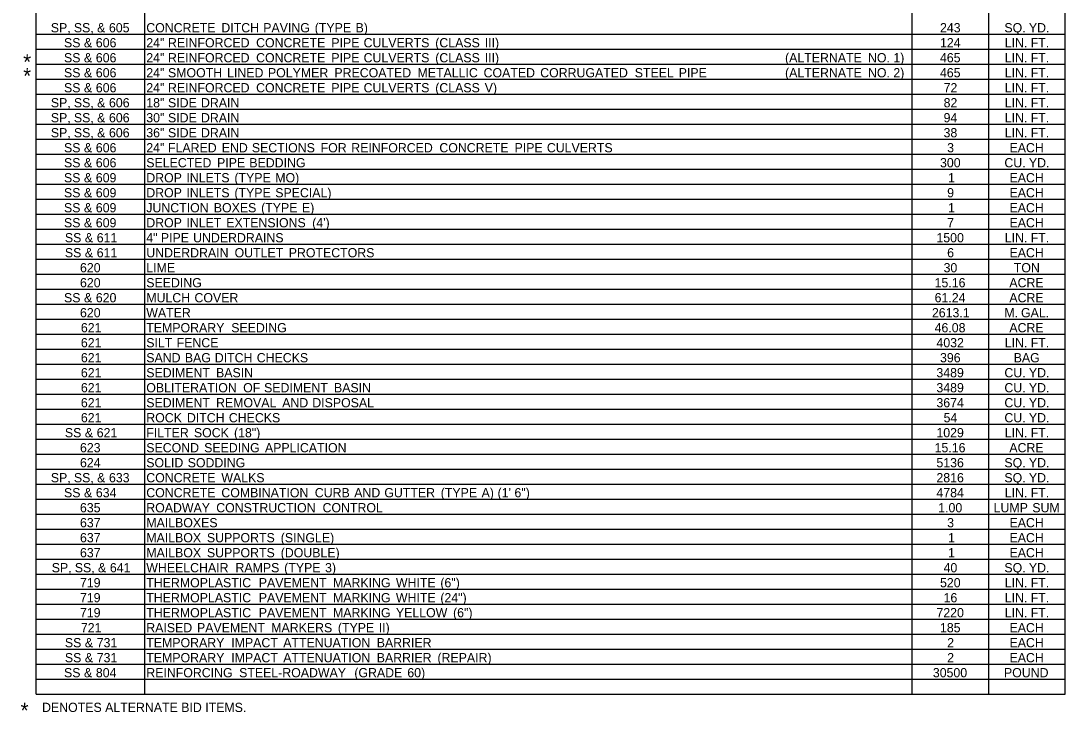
# Model space of a CAD drawing. Extents: x 1197542 to 1207068, y 230488 to 237324.
# Drawn here: x 1205572 to 1206251, y 231811 to 232261 of the extents above; entities that cross this region are included whole.
import ezdxf

# ---------------------------------------------------------------- set-up
doc = ezdxf.new("R2010")
doc.units = 0
doc.layers.add('Default', color=7, linetype='Continuous')

msp = doc.modelspace()

# ---------------------------------------------------------------- linework, layer by layer
at = {"layer": 'Default'}
for p, q in [((1205581.41, 231823.15), (1205581.41, 232690.9)), ((1205652.09, 231823.15), (1205652.09, 232690.9)), ((1206151.29, 231823.15), (1206151.29, 232690.9)), ((1206201.02, 231823.15), (1206201.02, 232690.9)), ((1206201.02, 231823.15), (1206201.02, 232690.9)), ((1206250.74, 231823.15), (1206250.74, 232690.9)), ((1205652.09, 231823.15), (1205652.09, 232661.65)), ((1206151.29, 231823.15), (1206151.29, 232661.65)), ((1205581.41, 232252.15), (1206250.74, 232252.15)), ((1205581.41, 232242.4), (1206250.74, 232242.4)), ((1205581.41, 232232.65), (1206250.74, 232232.65)), ((1205581.41, 232222.9), (1206250.74, 232222.9)), ((1205581.41, 232213.15), (1206250.74, 232213.15)), ((1205581.41, 232203.4), (1206250.74, 232203.4)), ((1205581.41, 232193.65), (1206250.74, 232193.65)), ((1205581.41, 232183.9), (1206250.74, 232183.9)), ((1205581.41, 232174.15), (1206250.74, 232174.15)), ((1205581.41, 232164.4), (1206250.74, 232164.4)), ((1205581.41, 232154.65), (1206250.74, 232154.65)), ((1205581.41, 232144.9), (1206250.74, 232144.9)), ((1205581.41, 232135.15), (1206250.74, 232135.15)), ((1205581.41, 232125.4), (1206250.74, 232125.4)), ((1205581.41, 232115.65), (1206250.74, 232115.65)), ((1205581.41, 232105.9), (1206250.74, 232105.9)), ((1205581.41, 232096.15), (1206250.74, 232096.15)), ((1205581.41, 232086.4), (1206250.74, 232086.4)), ((1205581.41, 232076.65), (1206250.74, 232076.65)), ((1205581.41, 232066.9), (1206250.74, 232066.9)), ((1205581.41, 232057.15), (1206250.74, 232057.15)), ((1205581.41, 232047.4), (1206250.74, 232047.4)), ((1205581.41, 232037.65), (1206250.74, 232037.65)), ((1205581.41, 232027.9), (1206250.74, 232027.9)), ((1205581.41, 232018.15), (1206250.74, 232018.15)), ((1205581.41, 232008.4), (1206250.74, 232008.4)), ((1205581.41, 231998.65), (1206250.74, 231998.65)), ((1205581.41, 231988.9), (1206250.74, 231988.9)), ((1205581.41, 231979.15), (1206250.74, 231979.15)), ((1205581.41, 231969.4), (1206250.74, 231969.4)), ((1205581.41, 231959.65), (1206250.74, 231959.65)), ((1205581.41, 231949.9), (1206250.74, 231949.9)), ((1205581.41, 231940.15), (1206250.74, 231940.15)), ((1205581.41, 231930.4), (1206250.74, 231930.4)), ((1205581.41, 231920.65), (1206250.74, 231920.65)), ((1205581.41, 231910.9), (1206250.74, 231910.9)), ((1205581.41, 231901.15), (1206250.74, 231901.15)), ((1205581.41, 231891.4), (1206250.74, 231891.4)), ((1205581.41, 231881.65), (1206250.74, 231881.65)), ((1205581.41, 231871.9), (1206250.74, 231871.9)), ((1205581.41, 231862.15), (1206250.74, 231862.15)), ((1205581.41, 231852.4), (1206250.74, 231852.4)), ((1205581.41, 231842.65), (1206250.74, 231842.65)), ((1205581.41, 231832.9), (1206250.74, 231832.9)), ((1205581.41, 231823.15), (1206250.74, 231823.15))]:
    msp.add_line(p, q, dxfattribs=at)

# ---------------------------------------------------------------- texts
for s, height, p in [('SP,', 6, (1205590.97, 232253.35)), (' SS,', 6, (1205603.73, 232253.35)), (' &', 6, (1205618.83, 232253.35)), (' 605', 6, (1205626.56, 232253.35)), ('CONCRETE', 6, (1205653.07, 232253.35)), (' DITCH', 6, (1205699.67, 232253.35)), (' PAVING', 6, (1205726.93, 232253.35)), (' (TYPE', 6, (1205760.42, 232253.35)), (' B)', 6, (1205786.99, 232253.35)), ('243', 6, (1206169.36, 232253.35)), ('SQ.', 6, (1206211.24, 232253.35)), (' YD.', 6, (1206224.95, 232253.35)), ('SS', 6, (1205599.55, 232243.6)), (' &', 6, (1205610.29, 232243.6)), (' 606', 6, (1205618.02, 232243.6)), ('24"', 6, (1205653.07, 232243.6)), (' REINFORCED', 6, (1205664.97, 232243.6)), (' CONCRETE', 6, (1205722.28, 232243.6)), (' PIPE', 6, (1205771.21, 232243.6)), (' CULVERTS', 6, (1205792.2, 232243.6)), (' (CLASS', 6, (1205838.81, 232243.6)), (' III)', 6, (1205870.98, 232243.6)), ('124', 6, (1206169.37, 232243.6)), ('LIN.', 6, (1206211.48, 232243.6)), (' FT.', 6, (1206226.12, 232243.6)), ('*', 10, (1205572.99, 232229.09)), ('SS', 6, (1205599.55, 232233.85)), (' &', 6, (1205610.29, 232233.85)), (' 606', 6, (1205618.02, 232233.85)), ('24"', 6, (1205653.07, 232233.85)), (' REINFORCED', 6, (1205664.97, 232233.85)), (' CONCRETE', 6, (1205722.28, 232233.85)), (' PIPE', 6, (1205771.21, 232233.85)), (' CULVERTS', 6, (1205792.2, 232233.85)), (' (CLASS', 6, (1205838.81, 232233.85)), (' III)', 6, (1205870.98, 232233.85)), ('(ALTERNATE', 6, (1206068.57, 232233.85)), (' NO.', 6, (1206120.29, 232233.85)), (' 1)', 6, (1206136.79, 232233.85)), ('465', 6, (1206169.33, 232233.85)), ('LIN.', 6, (1206211.48, 232233.85)), (' FT.', 6, (1206226.12, 232233.85)), ('*', 10, (1205572.99, 232220.1)), ('SS', 6, (1205599.55, 232224.1)), (' &', 6, (1205610.29, 232224.1)), (' 606', 6, (1205618.02, 232224.1)), ('24"', 6, (1205653.07, 232224.1)), (' SMOOTH', 6, (1205664.97, 232224.1)), (' LINED', 6, (1205703.42, 232224.1)), (' POLYMER', 6, (1205729.99, 232224.1)), (' PRECOATED', 6, (1205773.2, 232224.1)), (' METALLIC', 6, (1205827.26, 232224.1)), (' COATED', 6, (1205870.25, 232224.1)), (' CORRUGATED', 6, (1205907.07, 232224.1)), (' STEEL', 6, (1205968.57, 232224.1)), (' PIPE', 6, (1205997.16, 232224.1)), ('(ALTERNATE', 6, (1206068.57, 232224.1)), (' NO.', 6, (1206120.29, 232224.1)), (' 2)', 6, (1206136.79, 232224.1)), ('465', 6, (1206169.33, 232224.1)), ('LIN.', 6, (1206211.48, 232224.1)), (' FT.', 6, (1206226.12, 232224.1)), ('SS', 6, (1205599.55, 232214.35)), (' &', 6, (1205610.29, 232214.35)), (' 606', 6, (1205618.02, 232214.35)), ('24"', 6, (1205653.07, 232214.35)), (' REINFORCED', 6, (1205664.97, 232214.35)), (' CONCRETE', 6, (1205722.28, 232214.35)), (' PIPE', 6, (1205771.21, 232214.35)), (' CULVERTS', 6, (1205792.2, 232214.35)), (' (CLASS', 6, (1205838.81, 232214.35)), (' V)', 6, (1205870.98, 232214.35)), ('72', 6, (1206171.72, 232214.35)), ('LIN.', 6, (1206211.48, 232214.35)), (' FT.', 6, (1206226.12, 232214.35)), ('SP,', 6, (1205590.99, 232204.6)), (' SS,', 6, (1205603.76, 232204.6)), (' &', 6, (1205618.85, 232204.6)), (' 606', 6, (1205626.58, 232204.6)), ('18"', 6, (1205653.07, 232204.6)), (' SIDE', 6, (1205664.97, 232204.6)), (' DRAIN', 6, (1205686.42, 232204.6)), ('82', 6, (1206171.72, 232204.6)), ('LIN.', 6, (1206211.48, 232204.6)), (' FT.', 6, (1206226.12, 232204.6)), ('SP,', 6, (1205590.99, 232194.85)), (' SS,', 6, (1205603.76, 232194.85)), (' &', 6, (1205618.85, 232194.85)), (' 606', 6, (1205626.58, 232194.85)), ('30"', 6, (1205653.07, 232194.85)), (' SIDE', 6, (1205664.97, 232194.85)), (' DRAIN', 6, (1205686.42, 232194.85)), ('94', 6, (1206171.7, 232194.85)), ('LIN.', 6, (1206211.48, 232194.85)), (' FT.', 6, (1206226.12, 232194.85)), ('SP,', 6, (1205590.99, 232185.1)), (' SS,', 6, (1205603.76, 232185.1)), (' &', 6, (1205618.85, 232185.1)), (' 606', 6, (1205626.58, 232185.1)), ('36"', 6, (1205653.07, 232185.1)), (' SIDE', 6, (1205664.97, 232185.1)), (' DRAIN', 6, (1205686.42, 232185.1)), ('38', 6, (1206171.68, 232185.1)), ('LIN.', 6, (1206211.48, 232185.1)), (' FT.', 6, (1206226.12, 232185.1)), ('SS', 6, (1205599.55, 232175.35)), (' &', 6, (1205610.29, 232175.35)), (' 606', 6, (1205618.02, 232175.35)), ('24"', 6, (1205653.07, 232175.35)), (' FLARED', 6, (1205664.97, 232175.35)), (' END', 6, (1205699.93, 232175.35)), (' SECTIONS', 6, (1205719.51, 232175.35)), (' FOR', 6, (1205764.26, 232175.35)), (' REINFORCED', 6, (1205784.17, 232175.35)), (' CONCRETE', 6, (1205841.48, 232175.35)), (' PIPE', 6, (1205890.41, 232175.35)), (' CULVERTS', 6, (1205911.4, 232175.35)), ('3', 6, (1206174.02, 232175.35)), ('EACH', 6, (1206214.57, 232175.35)), ('SS', 6, (1205599.55, 232165.6)), (' &', 6, (1205610.29, 232165.6)), (' 606', 6, (1205618.02, 232165.6)), ('SELECTED', 6, (1205653.07, 232165.6)), (' PIPE', 6, (1205696.88, 232165.6)), (' BEDDING', 6, (1205717.87, 232165.6)), ('300', 6, (1206169.37, 232165.6)), ('CU.', 6, (1206211.24, 232165.6)), (' YD.', 6, (1206224.95, 232165.6)), ('SS', 6, (1205599.54, 232155.85)), (' &', 6, (1205610.29, 232155.85)), (' 609', 6, (1205618.02, 232155.85)), ('DROP', 6, (1205653.07, 232155.85)), (' INLETS', 6, (1205676.93, 232155.85)), (' (TYPE', 6, (1205708.17, 232155.85)), (' MO)', 6, (1205734.74, 232155.85)), ('1', 6, (1206174.6, 232155.85)), ('EACH', 6, (1206214.57, 232155.85)), ('SS', 6, (1205599.54, 232146.1)), (' &', 6, (1205610.29, 232146.1)), (' 609', 6, (1205618.02, 232146.1)), ('DROP', 6, (1205653.07, 232146.1)), (' INLETS', 6, (1205676.93, 232146.1)), (' (TYPE', 6, (1205708.17, 232146.1)), (' SPECIAL)', 6, (1205734.74, 232146.1)), ('9', 6, (1206174.01, 232146.1)), ('EACH', 6, (1206214.57, 232146.1)), ('SS', 6, (1205599.54, 232136.35)), (' &', 6, (1205610.29, 232136.35)), (' 609', 6, (1205618.02, 232136.35)), ('JUNCTION', 6, (1205653.07, 232136.35)), (' BOXES', 6, (1205694.77, 232136.35)), (' (TYPE', 6, (1205725.55, 232136.35)), (' E)', 6, (1205752.12, 232136.35)), ('1', 6, (1206174.6, 232136.35)), ('EACH', 6, (1206214.57, 232136.35)), ('SS', 6, (1205599.54, 232126.6)), (' &', 6, (1205610.29, 232126.6)), (' 609', 6, (1205618.02, 232126.6)), ('DROP', 6, (1205653.07, 232126.6)), (' INLET', 6, (1205676.93, 232126.6)), (' EXTENSIONS', 6, (1205702.84, 232126.6)), (" (4')", 6, (1205758.78, 232126.6)), ('7', 6, (1206174.02, 232126.6)), ('EACH', 6, (1206214.57, 232126.6)), ('SS', 6, (1205600.13, 232116.85)), (' &', 6, (1205610.87, 232116.85)), (' 611', 6, (1205618.6, 232116.85)), ('4"', 6, (1205653.07, 232116.85)), (' PIPE', 6, (1205660.31, 232116.85)), (' UNDERDRAINS', 6, (1205681.3, 232116.85)), ('1500', 6, (1206167.04, 232116.85)), ('LIN.', 6, (1206211.48, 232116.85)), (' FT.', 6, (1206226.12, 232116.85)), ('SS', 6, (1205600.13, 232107.1)), (' &', 6, (1205610.87, 232107.1)), (' 611', 6, (1205618.6, 232107.1)), ('UNDERDRAIN', 6, (1205653.07, 232107.1)), (' OUTLET', 6, (1205708.28, 232107.1)), (' PROTECTORS', 6, (1205743.51, 232107.1)), ('6', 6, (1206174.02, 232107.1)), ('EACH', 6, (1206214.57, 232107.1)), ('620', 6, (1205609.96, 232097.35)), ('LIME', 6, (1205653.07, 232097.35)), ('30', 6, (1206171.7, 232097.35)), ('TON', 6, (1206217.37, 232097.35)), ('620', 6, (1205609.96, 232087.6)), ('SEEDING', 6, (1205653.07, 232087.6)), ('15.16', 6, (1206165.86, 232087.6)), ('ACRE', 6, (1206214.46, 232087.6)), ('SS', 6, (1205599.56, 232077.85)), (' &', 6, (1205610.31, 232077.85)), (' 620', 6, (1205618.03, 232077.85)), ('MULCH', 6, (1205653.07, 232077.85)), (' COVER', 6, (1205682.2, 232077.85)), ('61.24', 6, (1206165.87, 232077.85)), ('ACRE', 6, (1206214.46, 232077.85)), ('620', 6, (1205609.96, 232068.1)), ('WATER', 6, (1205653.07, 232068.1)), ('2613.1', 6, (1206164.11, 232068.1)), ('M.', 6, (1206211.24, 232068.1)), (' GAL.', 6, (1206219.82, 232068.1)), ('621', 6, (1205610.53, 232058.35)), ('TEMPORARY', 6, (1205653.07, 232058.35)), (' SEEDING', 6, (1205706.11, 232058.35)), ('46.08', 6, (1206165.86, 232058.35)), ('ACRE', 6, (1206214.46, 232058.35)), ('621', 6, (1205610.53, 232048.6)), ('SILT', 6, (1205653.07, 232048.6)), (' FENCE', 6, (1205670.6, 232048.6)), ('4032', 6, (1206167.06, 232048.6)), ('LIN.', 6, (1206211.48, 232048.6)), (' FT.', 6, (1206226.12, 232048.6)), ('621', 6, (1205610.53, 232038.85)), ('SAND', 6, (1205653.07, 232038.85)), (' BAG', 6, (1205675.92, 232038.85)), (' DITCH', 6, (1205695.42, 232038.85)), (' CHECKS', 6, (1205722.69, 232038.85)), ('396', 6, (1206169.36, 232038.85)), ('BAG', 6, (1206217.29, 232038.85)), ('621', 6, (1205610.53, 232029.1)), ('SEDIMENT', 6, (1205653.07, 232029.1)), (' BASIN', 6, (1205696.22, 232029.1)), ('3489', 6, (1206167.02, 232029.1)), ('CU.', 6, (1206211.24, 232029.1)), (' YD.', 6, (1206224.95, 232029.1)), ('621', 6, (1205610.53, 232019.35)), ('OBLITERATION', 6, (1205653.07, 232019.35)), (' OF', 6, (1205713.87, 232019.35)), (' SEDIMENT', 6, (1205727.46, 232019.35)), (' BASIN', 6, (1205772.94, 232019.35)), ('3489', 6, (1206167.02, 232019.35)), ('CU.', 6, (1206211.24, 232019.35)), (' YD.', 6, (1206224.95, 232019.35)), ('621', 6, (1205610.53, 232009.6)), ('SEDIMENT', 6, (1205653.07, 232009.6)), (' REMOVAL', 6, (1205696.22, 232009.6)), (' AND', 6, (1205739.25, 232009.6)), (' DISPOSAL', 6, (1205758.83, 232009.6)), ('3674', 6, (1206167.04, 232009.6)), ('CU.', 6, (1206211.24, 232009.6)), (' YD.', 6, (1206224.95, 232009.6)), ('621', 6, (1205610.53, 231999.85)), ('ROCK', 6, (1205653.07, 231999.85)), (' DITCH', 6, (1205677.27, 231999.85)), (' CHECKS', 6, (1205704.54, 231999.85)), ('54', 6, (1206171.7, 231999.85)), ('CU.', 6, (1206211.24, 231999.85)), (' YD.', 6, (1206224.95, 231999.85)), ('SS', 6, (1205600.13, 231990.1)), (' &', 6, (1205610.87, 231990.1)), (' 621', 6, (1205618.6, 231990.1)), ('FILTER', 6, (1205653.07, 231990.1)), (' SOCK', 6, (1205681.83, 231990.1)), (' (18")', 6, (1205707.9, 231990.1)), ('1029', 6, (1206167.02, 231990.1)), ('LIN.', 6, (1206211.48, 231990.1)), (' FT.', 6, (1206226.12, 231990.1)), ('623', 6, (1205609.95, 231980.35)), ('SECOND', 6, (1205653.07, 231980.35)), (' SEEDING', 6, (1205688.49, 231980.35)), (' APPLICATION', 6, (1205728.03, 231980.35)), ('15.16', 6, (1206165.86, 231980.35)), ('ACRE', 6, (1206214.46, 231980.35)), ('624', 6, (1205609.96, 231970.6)), ('SOLID', 6, (1205653.07, 231970.6)), (' SODDING', 6, (1205677.78, 231970.6)), ('5136', 6, (1206167.03, 231970.6)), ('SQ.', 6, (1206211.24, 231970.6)), (' YD.', 6, (1206224.95, 231970.6)), ('SP,', 6, (1205590.99, 231960.85)), (' SS,', 6, (1205603.76, 231960.85)), (' &', 6, (1205618.85, 231960.85)), (' 633', 6, (1205626.58, 231960.85)), ('CONCRETE', 6, (1205653.07, 231960.85)), (' WALKS', 6, (1205699.67, 231960.85)), ('2816', 6, (1206167.03, 231960.85)), ('SQ.', 6, (1206211.24, 231960.85)), (' YD.', 6, (1206224.95, 231960.85)), ('SS', 6, (1205599.56, 231951.1)), (' &', 6, (1205610.31, 231951.1)), (' 634', 6, (1205618.04, 231951.1)), ('CONCRETE', 6, (1205653.07, 231951.1)), (' COMBINATION', 6, (1205699.67, 231951.1)), (' CURB', 6, (1205760.46, 231951.1)), (' AND', 6, (1205786.1, 231951.1)), (' GUTTER', 6, (1205805.68, 231951.1)), (' (TYPE', 6, (1205842.37, 231951.1)), (' A)', 6, (1205868.94, 231951.1)), (" (1'", 6, (1205879.34, 231951.1)), (' 6")', 6, (1205890.33, 231951.1)), ('4784', 6, (1206167.04, 231951.1)), ('LIN.', 6, (1206211.48, 231951.1)), (' FT.', 6, (1206226.12, 231951.1)), ('635', 6, (1205609.93, 231941.35)), ('ROADWAY', 6, (1205653.07, 231941.35)), (' CONSTRUCTION', 6, (1205696.33, 231941.35)), (' CONTROL', 6, (1205765.5, 231941.35)), ('1.00', 6, (1206168.2, 231941.35)), ('LUMP', 6, (1206204.25, 231941.35)), (' SUM', 6, (1206227.18, 231941.35)), ('637', 6, (1205609.95, 231931.6)), ('MAILBOXES', 6, (1205653.07, 231931.6)), ('3', 6, (1206174.02, 231931.6)), ('EACH', 6, (1206214.57, 231931.6)), ('637', 6, (1205609.95, 231921.85)), ('MAILBOX', 6, (1205653.07, 231921.85)), (' SUPPORTS', 6, (1205690.28, 231921.85)), (' (SINGLE)', 6, (1205738.3, 231921.85)), ('1', 6, (1206174.6, 231921.85)), ('EACH', 6, (1206214.57, 231921.85)), ('637', 6, (1205609.95, 231912.1)), ('MAILBOX', 6, (1205653.07, 231912.1)), (' SUPPORTS', 6, (1205690.28, 231912.1)), (' (DOUBLE)', 6, (1205738.3, 231912.1)), ('1', 6, (1206174.6, 231912.1)), ('EACH', 6, (1206214.57, 231912.1)), ('SP,', 6, (1205591.57, 231902.35)), (' SS,', 6, (1205604.34, 231902.35)), (' &', 6, (1205619.43, 231902.35)), (' 641', 6, (1205627.16, 231902.35)), ('WHEELCHAIR', 6, (1205653.07, 231902.35)), (' RAMPS', 6, (1205708.85, 231902.35)), (' (TYPE', 6, (1205740.56, 231902.35)), (' 3)', 6, (1205767.13, 231902.35)), ('40', 6, (1206171.7, 231902.35)), ('SQ.', 6, (1206211.24, 231902.35)), (' YD.', 6, (1206224.95, 231902.35)), ('719', 6, (1205609.94, 231892.6)), ('THERMOPLASTIC', 6, (1205653.07, 231892.6)), (' PAVEMENT', 6, (1205724.01, 231892.6)), (' MARKING', 6, (1205772.29, 231892.6)), (' WHITE', 6, (1205813.22, 231892.6)), (' (6")', 6, (1205842.11, 231892.6)), ('520', 6, (1206169.37, 231892.6)), ('LIN.', 6, (1206211.48, 231892.6)), (' FT.', 6, (1206226.12, 231892.6)), ('719', 6, (1205609.94, 231882.85)), ('THERMOPLASTIC', 6, (1205653.07, 231882.85)), (' PAVEMENT', 6, (1205724.01, 231882.85)), (' MARKING', 6, (1205772.29, 231882.85)), (' WHITE', 6, (1205813.22, 231882.85)), (' (24")', 6, (1205842.11, 231882.85)), ('16', 6, (1206171.69, 231882.85)), ('LIN.', 6, (1206211.48, 231882.85)), (' FT.', 6, (1206226.12, 231882.85)), ('719', 6, (1205609.94, 231873.1)), ('THERMOPLASTIC', 6, (1205653.07, 231873.1)), (' PAVEMENT', 6, (1205724.01, 231873.1)), (' MARKING', 6, (1205772.29, 231873.1)), (' YELLOW', 6, (1205813.22, 231873.1)), (' (6")', 6, (1205850.39, 231873.1)), ('7220', 6, (1206167.04, 231873.1)), ('LIN.', 6, (1206211.48, 231873.1)), (' FT.', 6, (1206226.12, 231873.1)), ('721', 6, (1205610.53, 231863.35)), ('RAISED', 6, (1205653.07, 231863.35)), (' PAVEMENT', 6, (1205683.84, 231863.35)), (' MARKERS', 6, (1205732.12, 231863.35)), (' (TYPE', 6, (1205775.47, 231863.35)), (' II)', 6, (1205802.04, 231863.35)), ('185', 6, (1206169.33, 231863.35)), ('EACH', 6, (1206214.57, 231863.35)), ('SS', 6, (1205600.13, 231853.6)), (' &', 6, (1205610.87, 231853.6)), (' 731', 6, (1205618.6, 231853.6)), ('TEMPORARY', 6, (1205653.07, 231853.6)), (' IMPACT', 6, (1205706.11, 231853.6)), (' ATTENUATION', 6, (1205739.94, 231853.6)), (' BARRIER', 6, (1205800.74, 231853.6)), ('2', 6, (1206174.05, 231853.6)), ('EACH', 6, (1206214.57, 231853.6)), ('SS', 6, (1205600.13, 231843.85)), (' &', 6, (1205610.87, 231843.85)), (' 731', 6, (1205618.6, 231843.85)), ('TEMPORARY', 6, (1205653.07, 231843.85)), (' IMPACT', 6, (1205706.11, 231843.85)), (' ATTENUATION', 6, (1205739.94, 231843.85)), (' BARRIER', 6, (1205800.74, 231843.85)), (' (REPAIR)', 6, (1205840.23, 231843.85)), ('2', 6, (1206174.05, 231843.85)), ('EACH', 6, (1206214.57, 231843.85)), ('SS', 6, (1205599.56, 231834.1)), (' &', 6, (1205610.31, 231834.1)), (' 804', 6, (1205618.04, 231834.1)), ('REINFORCING', 6, (1205653.07, 231834.1)), (' STEEL-ROADWAY', 6, (1205711.23, 231834.1)), (' (GRADE', 6, (1205786.17, 231834.1)), (' 60)', 6, (1205820.65, 231834.1)), ('30500', 6, (1206164.71, 231834.1)), ('POUND', 6, (1206210.97, 231834.1)), ('*', 10, (1205571.29, 231807.55)), ('DENOTES ALTERNATE BID ITEMS.', 6, (1205585.3, 231811.55))]:
    msp.add_text(s, height=height, dxfattribs=at).set_placement(p)

doc.saveas('drawing.dxf')
